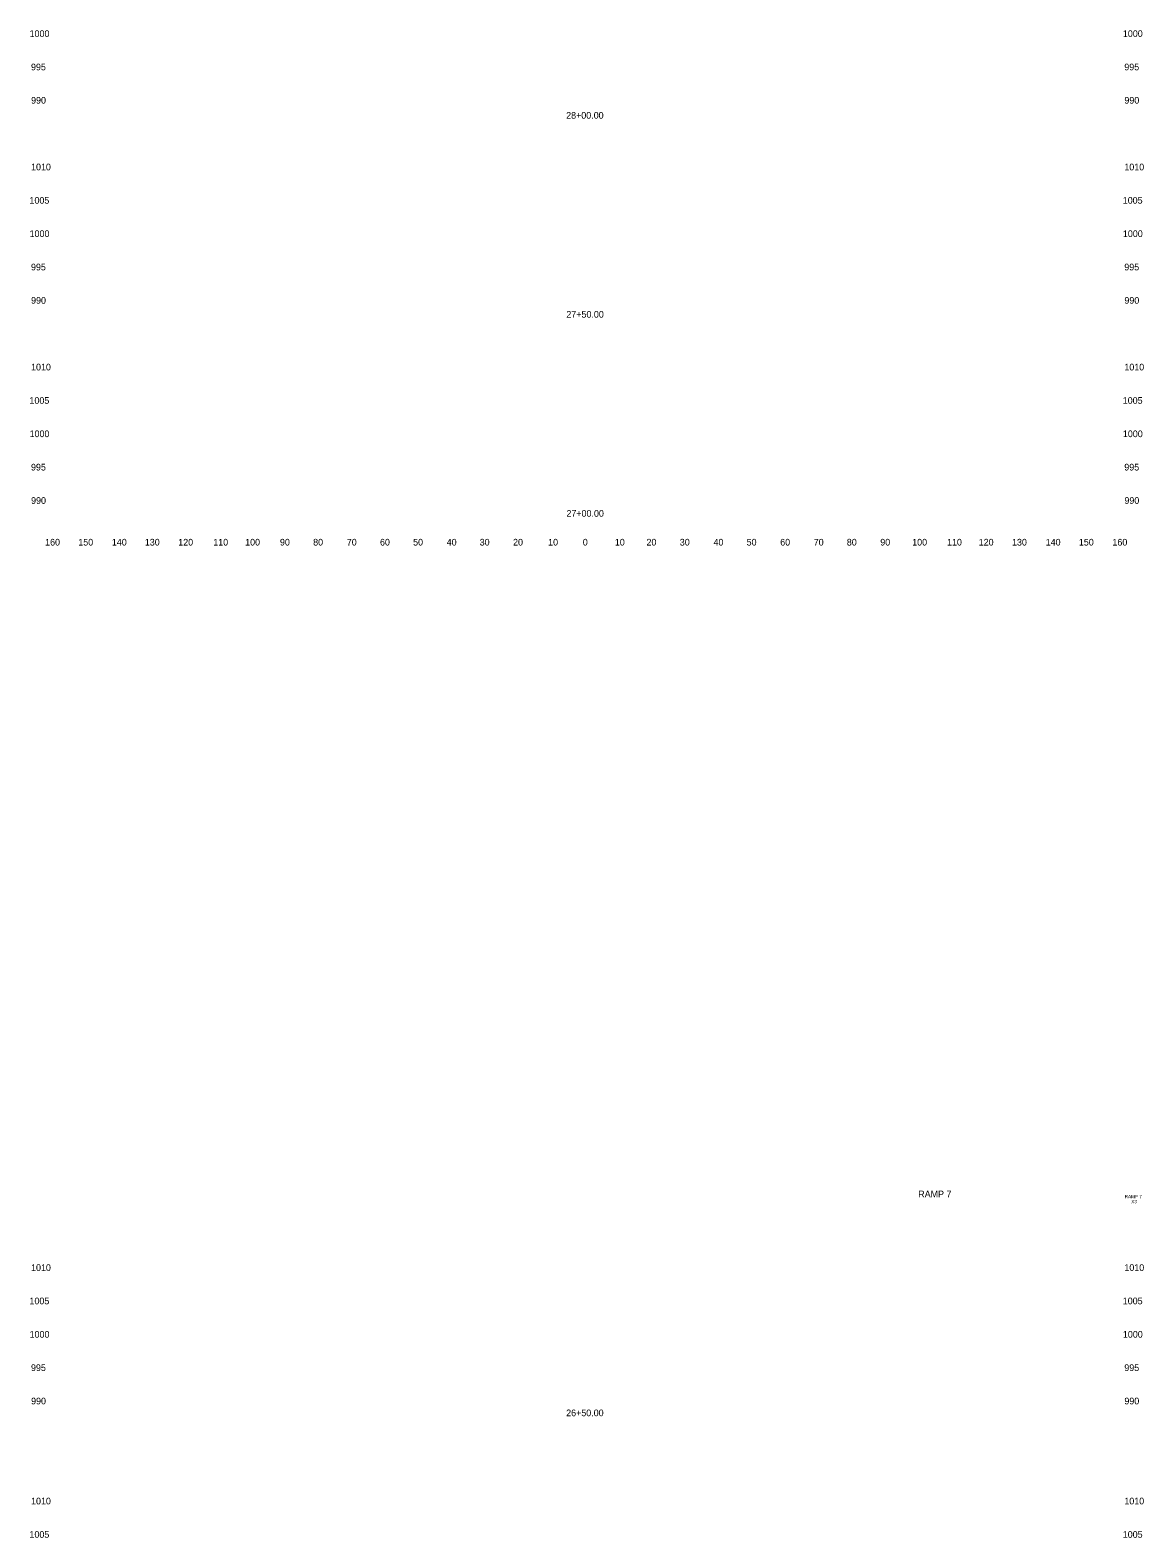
# Model space of a CAD drawing. Extents: x 4994 to 5701, y 4992 to 6804.
# Drawn here: x 4993.6 to 5327.5, y 5900 to 6352 of the extents above; entities that cross this region are included whole.
import ezdxf

# ---------------------------------------------------------------- set-up
doc = ezdxf.new("R2010")
doc.units = 0
for name, color, linetype in [('CLS_Search_Dist', 7, 'Continuous'), ('RD_XE_Ground', 7, 'Continuous'), ('UC_PD_Text', 7, 'Continuous')]:
    doc.layers.add(name, color=color, linetype=linetype)

msp = doc.modelspace()

# ---------------------------------------------------------------- texts
at = {"layer": 'CLS_Search_Dist'}
for s, p in [('1000', (4993.44, 6350)), ('1000', (5321.24, 6350)), ('995', (4993.86, 6340)), ('995', (5321.66, 6340)), ('990', (4993.89, 6330)), ('990', (5321.69, 6330)), ('1010', (4993.88, 6310)), ('1010', (5321.68, 6310)), ('1005', (4993.4, 6300)), ('1005', (5321.2, 6300)), ('1000', (4993.44, 6290)), ('1000', (5321.24, 6290)), ('995', (4993.86, 6280)), ('995', (5321.66, 6280)), ('990', (4993.89, 6270)), ('990', (5321.69, 6270)), ('1010', (4993.88, 6250)), ('1010', (5321.68, 6250)), ('1005', (4993.4, 6240)), ('1005', (5321.2, 6240)), ('1000', (4993.44, 6230)), ('1000', (5321.24, 6230)), ('995', (4993.86, 6220)), ('995', (5321.66, 6220)), ('990', (4993.89, 6210)), ('990', (5321.69, 6210)), ('160', (4998.1, 6197.5)), ('150', (5008.04, 6197.5)), ('140', (5018.1, 6197.5)), ('130', (5027.99, 6197.5)), ('120', (5038.01, 6197.5)), ('110', (5048.51, 6197.5)), ('100', (5058.07, 6197.5)), ('90', (5068.5, 6197.5)), ('80', (5078.46, 6197.5)), ('70', (5088.54, 6197.5)), ('60', (5098.5, 6197.5)), ('50', (5108.43, 6197.5)), ('40', (5118.5, 6197.5)), ('30', (5128.39, 6197.5)), ('20', (5138.4, 6197.5)), ('10', (5148.91, 6197.5)), ('0', (5159.3, 6197.5)), ('0', (5159.3, 6197.5)), ('10', (5168.91, 6197.5)), ('20', (5178.4, 6197.5)), ('30', (5188.39, 6197.5)), ('40', (5198.5, 6197.5)), ('50', (5208.43, 6197.5)), ('60', (5218.5, 6197.5)), ('70', (5228.54, 6197.5)), ('80', (5238.46, 6197.5)), ('90', (5248.5, 6197.5)), ('100', (5258.07, 6197.5)), ('110', (5268.51, 6197.5)), ('120', (5278.01, 6197.5)), ('130', (5287.99, 6197.5)), ('140', (5298.1, 6197.5)), ('150', (5308.04, 6197.5)), ('160', (5318.1, 6197.5)), ('1010', (4993.88, 5980)), ('1010', (5321.68, 5980)), ('1005', (4993.4, 5970)), ('1005', (5321.2, 5970)), ('1000', (4993.44, 5960)), ('1000', (5321.24, 5960)), ('995', (4993.86, 5950)), ('995', (5321.66, 5950)), ('990', (4993.89, 5940)), ('990', (5321.69, 5940)), ('1010', (4993.88, 5910)), ('1010', (5321.68, 5910)), ('1005', (4993.4, 5900)), ('1005', (5321.2, 5900))]:
    msp.add_text(s, height=2, dxfattribs=at).set_placement(p)
at = {"layer": 'RD_XE_Ground'}
for s, p in [('28+00.00', (5154.32, 6325.49)), ('27+50.00', (5154.37, 6265.82)), ('27+00.00', (5154.4, 6206.13)), ('26+50.00', (5154.32, 5936.44))]:
    msp.add_text(s, height=2, dxfattribs=at).set_placement(p)
at = {"layer": 'UC_PD_Text'}
for s, height, p in [('RAMP 7', 2, (5259.88, 6002.06)), ('RAMP 7', 1, (5321.78, 6001.8)), ('X3', 1, (5323.74, 6000.3))]:
    msp.add_text(s, height=height, dxfattribs=at).set_placement(p)

doc.saveas('drawing.dxf')
